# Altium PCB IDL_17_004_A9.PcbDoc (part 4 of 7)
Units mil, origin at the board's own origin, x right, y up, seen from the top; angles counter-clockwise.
Board outline 9493.25 x 7199.68 mil, 6 copper layers (Top Layer - SIG1, Layer 2 - GND1, Layer 3 - PWR1, Layer 4 - PWR2, Layer 5 - GND2, Bottom Layer - SIG2), stack 60.592 mil thick; 403 components, 274 nets, 1834 pads, 1849 vias.
Unrouted connection lines stored in the file: 1.
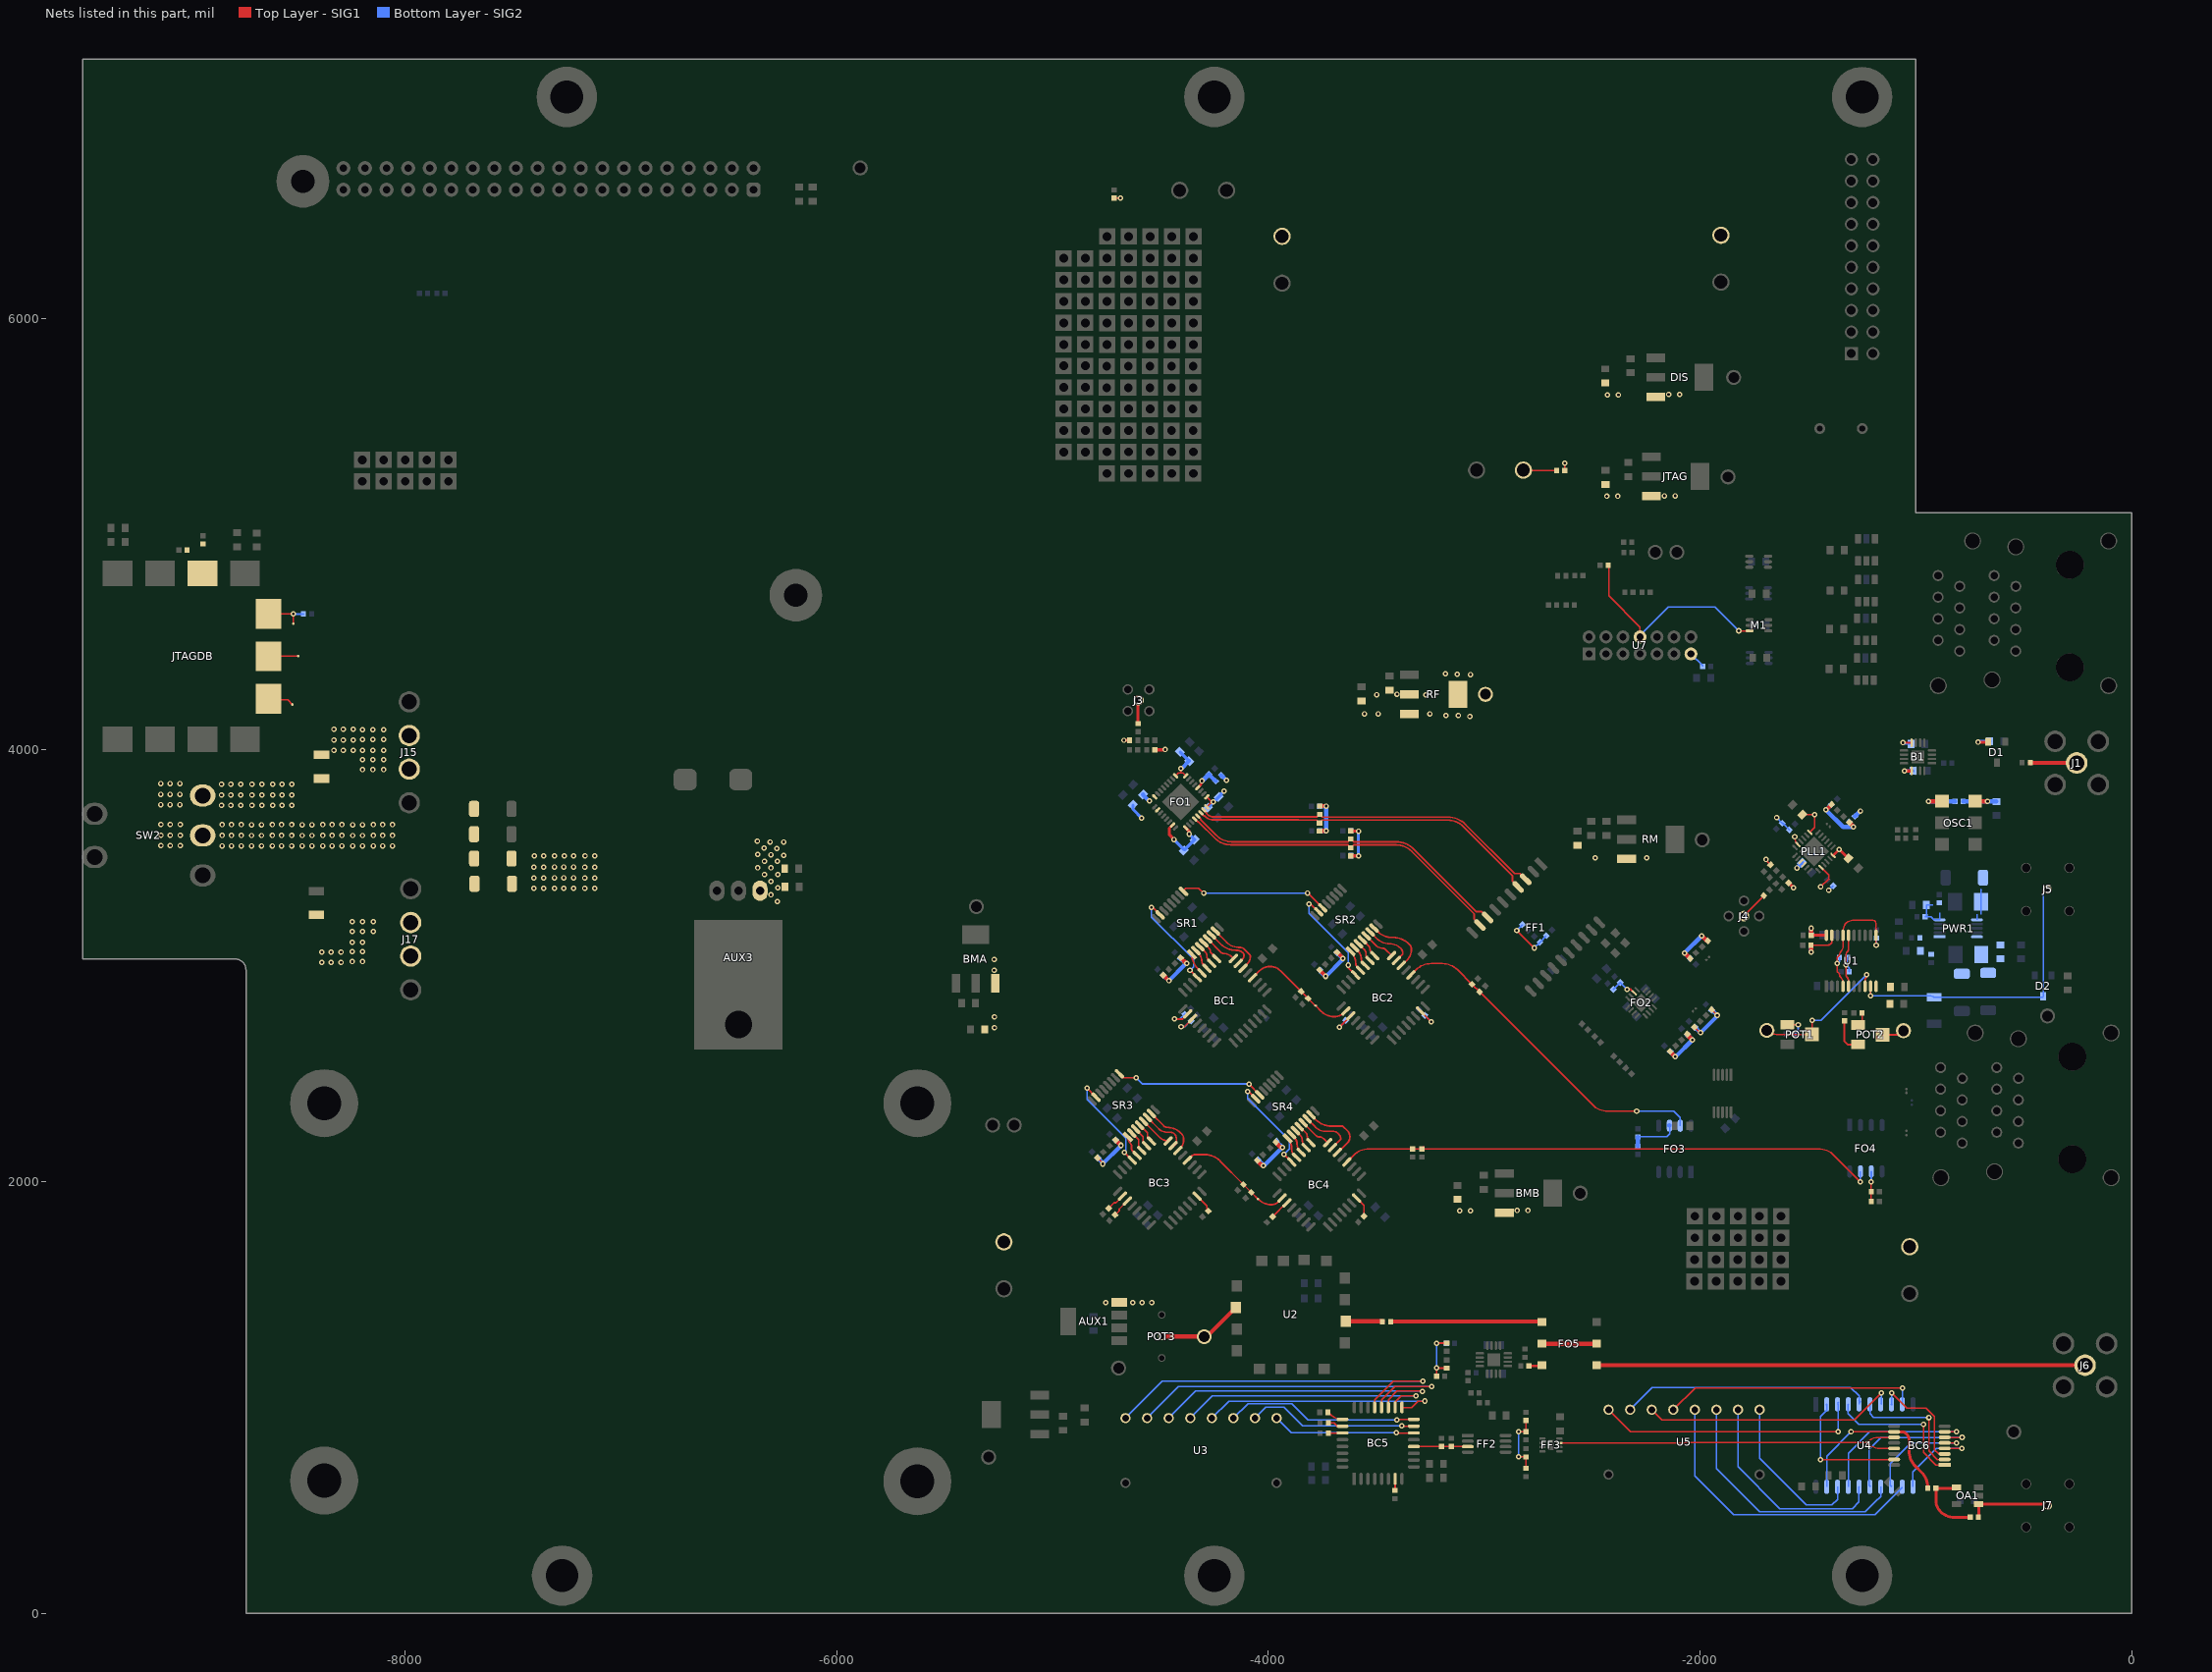
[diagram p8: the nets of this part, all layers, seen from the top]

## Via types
v1: diameter 25, hole 12, Top Layer - SIG1 to Bottom Layer - SIG2, tented both sides, 1502 vias
v2: diameter 25, hole 12, Top Layer - SIG1 to Bottom Layer - SIG2, 184 vias
v3: diameter 25.59, hole 11.81, Top Layer - SIG1 to Bottom Layer - SIG2, tented both sides, 163 vias

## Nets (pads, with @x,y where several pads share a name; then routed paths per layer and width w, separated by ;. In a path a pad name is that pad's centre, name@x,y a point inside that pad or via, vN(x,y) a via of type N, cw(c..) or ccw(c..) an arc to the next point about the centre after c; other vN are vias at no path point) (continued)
NetBC1_12: BC1.12 BC2.26 R65.1 R69.1 TP11.1 | length 575.6
  Top Layer - SIG1 w8: BC1.12@-4073.26,2944.9 -4041.26,2976.91 cw(c-3992.36,2928.02) -3992.36,2997.16 cw(c-3992.36,2928.12) -3943.54,2976.94 -3932.7,2966.09 R65.1@-3847.63,2881.02 -3816.38,2849.78 cw(c-3817.34,2848.82) R69.1@-3815.98,2848.82 -3783.52,2816.35 ccw(c-3781.35,2818.53) TP11.1@-3781.35,2815.45 -3755.1,2789.2 ccw(c-3695.35,2848.95) -3695.35,2764.45 ccw(c-3695.35,2832.52) -3647.22,2784.39 BC2.26@-3640.66,2790.95 ; BC1.12@-4055.93,2962.01 BC1.12@-4071.75,2946.19 ; BC1.12@-4071.75,2946.19 ccw(c-4001.14,2875.38) -4071.86,2946.09 -4073.15,2944.8 BC1.12@-4071.75,2946.19
NetBC1_14: BC1.14 SR1.7 | length 275.2
  Top Layer - SIG1 w8: SR1.7@-4245.62,3161.36 -4192.47,3108.21 ccw(c-4140.08,3160.6) -4140.08,3086.51 ccw(c-4137.68,3088.9) -4137.68,3085.52 -4133.6,3085.52 cw(c-4133.6,3051.63) -4109.64,3075.59 -4087.08,3053.03 cw(c-4094.32,3045.79) -4084.08,3045.79 -4084.08,3041.03 cw(c-4127.74,3041.03) -4096.87,3010.16 BC1.14@-4117.69,2989.34
NetBC1_15: BC1.15 SR1.6 | length 234.1
  Top Layer - SIG1 w8: SR1.6@-4263.71,3143.26 -4221.76,3101.31 ccw(c-4151.08,3171.99) -4151.08,3072.03 -4147.05,3072.03 cw(c-4147.05,3031.06) -4118.08,3060.03 cw(c-4130.15,3047.96) -4113.08,3047.96 -4113.08,3047.03 cw(c-4133.7,3047.03) -4119.12,3032.45 BC1.15@-4139.96,3011.61
NetBC1_16: BC1.16 SR1.5 | length 154.5
  Top Layer - SIG1 w8: SR1.5@-4281.81,3125.17 -4218.34,3061.7 ccw(c-4207.08,3072.96) -4207.08,3057.03 cw(c-4207.08,3004.66) -4170.05,3041.69 BC1.16@-4162.23,3033.88
NetBC1_17: BC1.17 SR1.4 | length 96.5
  Top Layer - SIG1 w8: SR1.4@-4299.9,3107.07 -4274.89,3082.06 cw(c-4288.91,3068.03) -4269.08,3068.03 ccw(c-4256.39,3068.03) -4265.36,3059.06 BC1.17@-4240.18,3033.88
NetBC1_18: BC1.18 SR1.3 | length 98.1
  Top Layer - SIG1 w8: SR1.3@-4318,3088.98 -4292.17,3063.15 cw(c-4309.28,3046.03) -4285.08,3046.03 ccw(c-4256.59,3046.03) -4276.74,3025.9 BC1.18@-4262.45,3011.61
NetBC1_19: BC1.19 SR1.2 | length 99.7
  Top Layer - SIG1 w8: SR1.2@-4336.09,3070.88 -4325.04,3059.82 cw(c-4366,3018.88) -4308.08,3018.88 ccw(c-4293.15,3018.88) BC1.19@-4303.71,3008.33 ; BC1.19@-4303.71,3008.32 BC1.19@-4284.72,2989.34
NetBC1_20: BC1.20 SR1.1 | length 101.3
  Top Layer - SIG1 w8: SR1.1@-4354.19,3052.79 ccw(c-4261.18,3052.79) -4326.95,2987.02 BC1.20@-4306.99,2967.07
NetBC1_21: BC1.21 SR1.15 | length 503.3
  Top Layer - SIG1 w6: v3(-4541.43,3271.28) -4541.43,3277.19 -4501.74,3237.49 SR1.15@-4501.74,3236.52 ; v3(-4363.27,2979.93) -4364.32,2980.98 -4365.45,2980.98 BC1.21@-4329.26,2944.8
  Bottom Layer - SIG2 w6: v3(-4541.43,3271.28) -4541.43,3274.83 -4541.63,3275.03 -4541.63,3225.81 -4346.75,3030.93 -4346.75,2996.45 v3(-4363.27,2979.93)
NetBC1_26: BC1.26 R68.1 | length 129
  Top Layer - SIG1 w8: v3(-4435.42,2753.84) -4397.73,2753.84 BC1.26@-4373.81,2777.76
  Bottom Layer - SIG2 w8: v3(-4435.42,2753.84) -4409.72,2753.84 R68.1@-4387.27,2776.29
NetBC1_27: BC1.27 R61.1 | length 125.9
  Top Layer - SIG1 w8: v3(-4404.35,2718.55) -4388.47,2718.55 BC1.27@-4351.54,2755.49
  Bottom Layer - SIG2 w8: v3(-4404.35,2718.55) -4387.7,2718.55 -4363.37,2742.88 cw(c-4357.32,2736.83) R61.1@-4357.32,2745.39
NetBC2_7: BC2.7 R64.1 | length 116.4
  Top Layer - SIG1 w8: BC2.7@-3295.46,2790.95 -3295.46,2790.08 v1(-3245.84,2740.47)
  Top Layer - SIG1 w20: v1(-3245.84,2740.47) v1@-3245.84,2743.12
  Bottom Layer - SIG2 w8: R64.1@-3275.09,2771.07 -3245.84,2741.82 v1(-3245.84,2740.47)
NetBC2_12: BC2.12 FO3.7 R66.1 R70.1 | length 1589.7
  Top Layer - SIG1 w6: BC2.12@-3340,2957.98 -3316.49,2981.49 cw(c-3245.78,2910.77) -3245.78,3010.77 -3194.48,3010.77 cw(c-3194.48,2910.77) -3123.77,2981.49 R70.1@-3057.01,2914.72 R66.1@-3021.65,2879.37 ; R66.1@-3021.65,2879.59 -2498.35,2356.29 ccw(c-2427.64,2427) -2427.64,2327 v3(-2294,2327)
  Bottom Layer - SIG2 w6: v3(-2294,2327) -2122.12,2327 -2092.5,2297.39 FO3.7@-2092.5,2259.71
NetBC2_14: BC2.14 SR2.7 | length 304
  Top Layer - SIG1 w8: SR2.7@-3510.77,3175.38 -3496.14,3160.74 ccw(c-3425.43,3231.45) -3425.43,3131.45 -3420.77,3131.45 cw(c-3420.77,3031.45) -3350.06,3102.16 -3345.12,3097.23 cw(c-3363.9,3078.45) -3337.35,3078.45 cw(c-3414.6,3078.45) -3359.97,3023.83 -3378.97,3004.83 cw(c-3384.54,3010.4) BC2.14@-3384.54,3002.52
NetBC2_15: BC2.15 SR2.6 | length 237.3
  Top Layer - SIG1 w8: SR2.6@-3528.87,3157.28 -3499.39,3127.8 ccw(c-3438.19,3189.01) -3438.19,3102.45 cw(c-3438.19,3030.41) -3387.25,3081.35 cw(c-3411.15,3057.45) -3377.35,3057.45 cw(c-3385.06,3057.45) -3379.6,3052.01 BC2.15@-3406.81,3024.79
NetBC2_16: BC2.16 SR2.5 | length 153.4
  Top Layer - SIG1 w8: SR2.5@-3546.97,3139.19 -3503.29,3095.51 ccw(c-3469.35,3129.46) -3469.35,3081.45 cw(c-3469.35,3067.26) -3459.31,3077.3 BC2.16@-3429.08,3047.07
NetBC2_17: BC2.17 SR2.4 | length 96.4
  Top Layer - SIG1 w8: SR2.4@-3565.06,3121.09 -3534.82,3090.85 cw(c-3548.02,3077.64) -3529.35,3077.64 ccw(c-3509.4,3077.64) -3523.5,3063.54 BC2.17@-3507.03,3047.07
NetBC2_18: BC2.18 SR2.3 | length 98
  Top Layer - SIG1 w8: SR2.3@-3583.16,3103 -3556.64,3076.49 cw(c-3576.68,3056.45) -3548.35,3056.45 ccw(c-3517.89,3056.45) BC2.18@-3539.44,3034.93 ; BC2.18@-3539.43,3034.92 BC2.18@-3529.3,3024.79
NetBC2_19: BC2.19 SR2.2 | length 99.6
  Top Layer - SIG1 w8: SR2.2@-3601.25,3084.9 -3583.46,3067.11 cw(c-3615.12,3035.45) -3570.35,3035.45 ccw(c-3536.17,3035.45) -3560.35,3011.3 BC2.19@-3551.57,3002.52
NetBC2_20: BC2.20 SR2.1 | length 101.1
  Top Layer - SIG1 w8: SR2.1@-3619.35,3066.81 -3618.93,3066.39 cw(c-3675.87,3009.45) -3595.35,3009.45 ccw(c-3576.76,3009.45) -3589.9,2996.31 BC2.20@-3573.84,2980.25
NetBC2_21: BC2.21 SR2.15 | length 479
  Top Layer - SIG1 w6: v3(-3812.35,3286.45) -3811.35,3285.45 -3801.8,3285.45 SR2.15@-3766.89,3250.54 ; v3(-3629.35,3003.45) -3629.35,2991.21 BC2.21@-3596.12,2957.98
  Bottom Layer - SIG2 w6: v3(-3812.35,3286.45) -3811.35,3286.45 -3811.35,3243.45 -3629.35,3061.45 v3(-3629.35,3003.45)
NetBC2_27: BC2.27 R62.1 | length 118.8
  Top Layer - SIG1 w8: v1(-3670.94,2716) -3618.39,2768.56 BC2.27@-3618.39,2768.68
  Top Layer - SIG1 w20: v1(-3670.94,2716) v1@-3670.94,2716.12
  Bottom Layer - SIG2 w8: v1(-3670.94,2716) -3642.23,2744.71 R62.1@-3642.23,2748.22
  Bottom Layer - SIG2 w20: v1(-3670.94,2716) v1@-3670.94,2716.12
NetBC3_7: BC3.7 R80.1 | length 82.1
  Top Layer - SIG1 w6: BC3.7@-4330.41,1933.06 -4284.61,1887.26 R80.1@-4284.61,1869.95
NetBC3_12: BC3.12 BC4.26 R82.1 R86.1 TP14.1 | length 542.6
  Top Layer - SIG1 w8: BC3.12@-4374.95,2100.09 -4356.99,2118.05 cw(c-4338.55,2099.61) -4338.55,2125.69 -4294.17,2125.69 cw(c-4294.17,2025.69) -4223.46,2096.4 ccw(c-4219.19,2096.4) -4222.21,2093.39 R86.1@-4115.82,1987 -4115.55,1987 R82.1@-4079.19,1950.63 -4048.23,1919.68 TP14.1@-4048.23,1919.59 ; TP14.1@-4044.22,1917.16 ccw(c-3987.55,1973.83) -3987.55,1893.69 ccw(c-3987.55,1941.79) -3953.54,1907.78 BC4.26@-3936.75,1924.57
NetBC3_14: BC3.14 SR3.7 | length 263.2
  Top Layer - SIG1 w8: SR3.7@-4542.21,2316.35 -4483.92,2258.05 ccw(c-4468.55,2273.42) -4468.55,2251.69 cw(c-4468.55,2162.36) -4405.39,2225.53 -4403.55,2223.69 cw(c-4430.11,2197.13) -4392.55,2197.13 -4392.55,2192.69 cw(c-4443.53,2192.69) -4407.48,2156.65 BC3.14@-4419.5,2144.63
NetBC3_15: BC3.15 SR3.6 | length 219.4
  Top Layer - SIG1 w8: SR3.6@-4560.68,2298.25 -4506.66,2244.23 ccw(c-4471.55,2279.34) -4471.55,2229.69 -4455.55,2229.69 cw(c-4455.55,2200.69) -4426.55,2200.69 -4426.55,2182.12 cw(c-4441.77,2182.12) BC3.15@-4441.77,2166.91
NetBC3_16: BC3.16 SR3.5 | length 150
  Top Layer - SIG1 w8: SR3.5@-4578.78,2280.16 -4504.6,2205.98 ccw(c-4464.04,2246.54) BC3.16@-4464.04,2189.18
NetBC3_17: BC3.17 SR3.4 | length 95.6
  Top Layer - SIG1 w6: SR3.4@-4596.87,2262.06 -4561.11,2226.3 -4561.11,2208.3 BC3.17@-4541.99,2189.18
NetBC3_18: BC3.18 SR3.3 | length 98.1
  Top Layer - SIG1 w6: SR3.3@-4614.97,2243.97 -4580.79,2209.79 -4580.79,2183.44 BC3.18@-4564.26,2166.91
NetBC3_19: BC3.19 SR3.2 | length 100.5
  Top Layer - SIG1 w6: SR3.2@-4633.06,2225.87 -4601.46,2194.27 -4601.46,2159.57 BC3.19@-4586.53,2144.63
NetBC3_20: BC3.20 SR3.1 | length 100
  Top Layer - SIG1 w8: SR3.1@-4651.16,2207.77 -4651.16,2207.12 ccw(c-4608.12,2207.12) -4638.55,2176.69 cw(c-4650.63,2164.62) -4633.55,2164.62 -4633.55,2150.5 ccw(c-4625.38,2150.5) -4631.16,2144.72 BC3.20@-4608.8,2122.36
NetBC3_21: BC3.21 SR3.15 | length 484.6
  Top Layer - SIG1 w6: v3@-4840.64,2433.44 SR3.15@-4798.71,2391.51 ; v1(-4667.19,2136.21) BC3.21@-4631.07,2100.09
  Bottom Layer - SIG2 w6: v3(-4840.64,2433.46) -4840.64,2381.29 -4661.04,2201.69 -4661.04,2142.37 v1(-4667.19,2136.21)
NetBC3_26: BC3.26 R85.1 | length 91.3
  Top Layer - SIG1 w8: R85.1@-4740.13,1877.01 -4714.28,1902.87 -4705.8,1902.87 BC3.26@-4675.61,1933.06 ccw(c-4675.61,1937.65) BC3.26@-4672.37,1934.4
NetBC3_27: BC3.27 R78.1 | length 87.9
  Top Layer - SIG1 w8: R78.1@-4709.69,1846.32 -4690.88,1865.13 -4690.88,1873.44 -4653.54,1910.79 BC3.27@-4653.34,1910.79
NetBC4_7: BC4.7 R81.1 | length 98.6
  Top Layer - SIG1 w8: BC4.7@-3591.55,1924.57 -3556.87,1889.89 R81.1@-3556.87,1840.35
NetBC4_12: BC4.12 FO4.7 R83.2 R87.1 | length 2516.9
  Top Layer - SIG1 w6: BC4.12@-3636.09,2091.6 -3605.24,2122.46 cw(c-3534.53,2051.74) -3534.53,2151.74 R87.1@-3331.32,2151.74 ; R83.2@-3288.25,2151.83 -1451.25,2151.83 cw(c-1451.25,2051.83) -1380.54,2122.54 v3(-1258,2000)
  Top Layer - SIG1 w8: R87.1@-3331.32,2151.74 R83.2@-3288.33,2151.74 ; R83.2@-3289.25,2150.83 R83.2@-3288.33,2151.74 ; R83.2@-3280.68,2159.4 R83.2@-3288.25,2151.83 R83.2@-3288.33,2151.74
  Bottom Layer - SIG2 w6: v3(-1258,2000) FO4.7@-1258,2047.55
NetBC4_14: BC4.14 SR4.7 | length 321.2
  Top Layer - SIG1 w8: SR4.7@-3802.62,2309.64 -3779.97,2286.98 ccw(c-3709.26,2357.69) -3709.26,2257.69 -3659.55,2257.69 cw(c-3659.55,2248.03) -3652.73,2254.86 -3633.55,2235.69 cw(c-3660.11,2209.13) -3622.55,2209.13 -3622.55,2206.69 cw(c-3658.77,2206.69) -3633.16,2181.08 -3676.31,2137.94 cw(c-3680.63,2142.26) BC4.14@-3680.63,2136.14
NetBC4_15: BC4.15 SR4.6 | length 252.5
  Top Layer - SIG1 w8: SR4.6@-3820.72,2291.54 -3783.04,2253.86 cw(c-3784.21,2252.69) -3782.55,2252.69 ccw(c-3736.68,2298.56) -3736.68,2233.69 -3701.7,2233.69 cw(c-3701.7,2199.55) -3677.55,2223.69 -3673.75,2219.88 cw(c-3695.94,2197.69) -3664.55,2197.69 -3702.25,2159.99 ccw(c-3700.67,2158.42) BC4.15@-3702.9,2158.42
NetBC4_16: BC4.16 SR4.5 | length 149.9
  Top Layer - SIG1 w8: SR4.5@-3838.81,2273.45 -3779.78,2214.41 ccw(c-3763.55,2230.63) -3763.55,2207.69 cw(c-3763.55,2180.23) -3744.13,2199.65 BC4.16@-3725.18,2180.69
NetBC4_17: BC4.17 SR4.4 | length 95.5
  Top Layer - SIG1 w8: SR4.4@-3856.91,2255.35 cw(c-3856.91,2251.26) -3854.02,2254.16 -3824.55,2224.69 cw(c-3833.1,2216.15) -3821.02,2216.15 -3821.02,2215.69 ccw(c-3779.7,2215.69) -3808.92,2186.48 BC4.17@-3803.12,2180.69
NetBC4_18: BC4.18 SR4.3 | length 96.4
  Top Layer - SIG1 w8: SR4.3@-3875.01,2237.25 -3850.71,2212.96 cw(c-3867.97,2195.69) -3843.55,2195.69 ccw(c-3797.41,2195.69) -3830.04,2163.06 BC4.18@-3825.4,2158.42
NetBC4_19: BC4.19 SR4.2 | length 97.9
  Top Layer - SIG1 w8: SR4.2@-3893.1,2219.16 -3880.23,2206.29 cw(c-3910.83,2175.69) -3867.55,2175.69 ccw(c-3820.1,2175.69) -3853.65,2142.13 BC4.19@-3847.67,2136.14
NetBC4_20: BC4.20 SR4.1 | length 100.2
  Top Layer - SIG1 w8: SR4.1@-3911.19,2201.06 cw(c-3956.2,2156.06) -3892.55,2156.06 -3892.55,2149.69 ccw(c-3860.69,2149.69) -3883.22,2127.16 BC4.20@-3869.94,2113.87
NetBC4_21: BC4.21 SR4.15 | length 482.6
  Top Layer - SIG1 w6: v3(-4095.56,2418.69) -4092.63,2418.69 SR4.15@-4058.74,2384.8 ; v3(-3927.25,2127.35) -3927.25,2126.64 BC4.21@-3892.21,2091.6
  Bottom Layer - SIG2 w6: v3(-4095.56,2418.69) -4095.56,2385.23 -3902.64,2192.32 -3902.64,2151.96 v3(-3927.25,2127.35)
NetBC4_27: BC4.27 R79.1 | length 95.3
  Top Layer - SIG1 w6: BC4.27@-3914.48,1902.3 BC4.27@-3912.15,1902.3
  Top Layer - SIG1 w8: R79.1@-3980.03,1838.66 -3915.32,1903.36 BC4.27@-3913.88,1903.36
NetBC5_7: BC5.7 R97.2 | length 53.7
  Top Layer - SIG1 w8: R97.2@-3413.1,570.08 -3413.1,623.69 BC5.7@-3413,623.79
NetBC5_12: BC5.12 FF2.3 R98.1 R101.1 | length 250.3
  Top Layer - SIG1 w6: BC5.12@-3326.48,773.48 -3198.25,773.48 R98.1@-3197.58,774.16
  Top Layer - SIG1 w8: R98.1@-3197.58,774.16 R101.1@-3153.58,774.16 -3079.86,774.16 cw(c-3079.86,769.8) FF2.3@-3076.77,772.89
NetBC5_14: BC5.14 U3.8 | length 664.2
  Top Layer - SIG1 w6: v3(-3406.51,837.25) -3405.64,836.38 BC5.14@-3326.39,836.38
  Bottom Layer - SIG2 w6: U3.8@-3962.12,905 -3894.37,837.25 v3(-3406.51,837.25)
NetBC5_15: BC5.15 U3.7 | length 793.4
  Top Layer - SIG1 w6: v3(-3382.88,868.74) -3382.02,867.88 BC5.15@-3326.39,867.88
  Bottom Layer - SIG2 w6: U3.7@-4062.12,905 -4011.12,956 -3928.15,956 -3840.9,868.74 v3(-3382.88,868.74)
NetBC5_16: BC5.16 U3.6 | length 901.1
  Top Layer - SIG1 w6: v3(-3405.52,897.29) -3403.43,899.38 BC5.16@-3326.39,899.38
  Bottom Layer - SIG2 w6: U3.6@-4162.12,905 -4095.12,972 -3891.02,972 -3816.3,897.29 v3(-3405.52,897.29) v3@-3409.6,901.37
NetBC5_17: BC5.17 U3.5 | length 1138.5
  Top Layer - SIG1 w6: BC5.17@-3382.33,956.47 ccw(c-3379.54,956.47) BC5.17@-3381.51,954.49 -3336.7,954.49 -3307.19,984 v3(-3276.12,984)
  Bottom Layer - SIG2 w6: U3.5@-4262.12,905 -4183.12,984 v3(-3276.12,984)
NetBC5_18: BC5.18 U3.4 | length 1223.1
  Top Layer - SIG1 w6: BC5.18@-3413.33,954.82 BC5.18@-3413,955.14 ; BC5.18@-3413,954.49 BC5.18@-3413,955.14 ; BC5.18@-3412.33,955.82 BC5.18@-3413,955.14 ; v3(-3316.12,1008) -3383.4,1008 -3413,978.4 BC5.18@-3413,955.14
  Bottom Layer - SIG2 w6: U3.4@-4362.12,905 -4259.12,1008 v3(-3316.12,1008)
NetBC5_19: BC5.19 U3.3 | length 1438.7
  Top Layer - SIG1 w6: BC5.19@-3444.33,954.67 BC5.19@-3444.5,954.49 -3444.5,989.56 -3404.26,1029.8 -3286.92,1029.8 v3(-3286.12,1029)
  Bottom Layer - SIG2 w6: U3.3@-4462.12,905 -4337.33,1029.8 -3286.92,1029.8 v3(-3286.12,1029)
NetBC5_20: BC5.20 U3.2 | length 1670.9
  Top Layer - SIG1 w6: BC5.20@-3476,954.49 -3476,989.56 -3414.55,1051 v3(-3244.12,1051)
  Bottom Layer - SIG2 w6: U3.2@-4562.12,905 -4416.12,1051 v3(-3244.12,1051)
NetBC5_21: BC5.21 U3.1 | length 1743.1
  Top Layer - SIG1 w6: BC5.21@-3507.49,954.49 -3507.49,989.56 -3421.05,1076 v3(-3284.12,1076)
  Bottom Layer - SIG2 w6: U3.1@-4662.12,905 -4491.12,1076 v3(-3284.12,1076)
NetBC5_25: BC5.25 R99.2 | length 76.7
  Top Layer - SIG1 w6: R99.2@-3723.85,931.98 -3715.37,923.51 ccw(c-3657.1,981.8) BC5.25@-3657.1,899.38
NetBC5_26: BC5.26 R100.2 | length 71.5
  Top Layer - SIG1 w6: R100.2@-3722.74,881.98 -3695.23,881.98 -3681.13,867.88 BC5.26@-3657.1,867.88
NetBC5_27: BC5.27 R96.2 | length 68.1
  Top Layer - SIG1 w6: R96.2@-3724.74,838.04 ccw(c-3720.75,842.03) -3720.75,836.38 BC5.27@-3657.1,836.38
NetBC6_1: BC6.1 U4.4 | length 670.5
  Top Layer - SIG1 w6: v1(-965.84,875.92) -965.84,745.76 -908.01,687.93 BC6.1@-867.35,687.93
  Bottom Layer - SIG2 w6: U4.4@-1313.84,964.29 -1312.6,965.53 U4.4@-1314.79,967.71 ; U4.4@-1313.79,968.71 U4.4@-1314.79,967.71 ; v1(-965.84,875.92) -1265.01,875.92 -1314.79,925.7 U4.4@-1314.79,967.71
NetBC6_2: BC6.2 U4.6 | length 582.9
  Top Layer - SIG1 w6: v3(-940.84,907.16) -940.84,752.45 -901.91,713.52 BC6.2@-867.35,713.52
  Bottom Layer - SIG2 w6: U4.6@-1213.84,962.73 U4.6@-1213.79,962.78 ; v3(-940.84,907.16) -1195.84,907.16 -1213.79,925.12 U4.6@-1213.79,962.78 ; U4.6@-1213.79,962.78 U4.6@-1213.79,968.71 -1214.79,969.71 -1214.97,969.9 -1213.99,970.88 -1209.84,966.73 U4.6@-1213.79,962.78
NetBC6_3: BC6.3 U4.8 | length 518.3
  Top Layer - SIG1 w6: v1(-1113.59,1022.1) -1042.66,951.16 -954.01,951.16 -914.69,911.84 -914.69,758.24 -895.56,739.11 BC6.3@-867.35,739.11 ccw(c-865.3,739.11) BC6.3@-865.3,737.06
  Bottom Layer - SIG2 w6: U4.8@-1114.79,969.71 -1114.79,967.22 cw(c-1114.79,966.22) -1113.79,966.22 -1111.62,968.38 -1113.59,970.35 v1(-1113.59,1022.1)
NetBC6_4: BC6.4 U4.11 | length 423.3
  Top Layer - SIG1 w6: BC6.4@-867.35,764.7 -867.35,765.21 v1(-786.82,765.21)
  Bottom Layer - SIG2 w6: U4.11@-1015.17,586.82 -1015.17,654.83 -904.79,765.21 v1(-786.82,765.21) v1@-786.97,765.06
NetBC6_5: BC6.5 U4.13 | length 513.2
  Top Layer - SIG1 w6: BC6.5@-867.35,790.29 -867.35,789.82 v3(-812.41,789.82)
  Bottom Layer - SIG2 w6: U4.13@-1113.79,586.82 -1120.48,593.52 -1120.48,694.18 -1024.84,789.82 v3(-812.41,789.82)
NetBC6_6: BC6.6 U4.15 | length 711.4
  Top Layer - SIG1 w6: BC6.6@-867.35,815.88 v3(-786.35,815.88)
  Bottom Layer - SIG2 w6: U4.15@-1210.05,586.82 -1216.94,593.71 -1216.94,761.06 -1162.12,815.88 v3(-786.35,815.88)
NetBC6_7: BC6.7 U4.17 | length 753.6
  Top Layer - SIG1 w6: BC6.7@-867.35,841.47 -867.35,841.98 v3(-812.41,841.98)
  Bottom Layer - SIG2 w6: U4.17@-1313.79,586.82 -1313.79,742.38 -1214.18,841.98 v3(-812.41,841.98)
NetBC6_10: BC6.10 R106.1 U4.19 | length 839.1
  Top Layer - SIG1 w6: v1(-1300.53,841.47) BC6.10@-1101.6,841.47
  Top Layer - SIG1 w13.5: BC6.10@-1101.6,841.47 -1067.32,841.47 cw(c-1067.32,809.34) -1044.6,832.06 cw(c-1073.57,803.09) -1032.6,803.09 -1032.6,753.48 ccw(c-932.6,753.48) -1003.31,682.77 -974.88,654.34 cw(c-1045.59,583.63) R106.1@-945.59,583.63
  Bottom Layer - SIG2 w6: U4.19@-1413.79,586.82 -1413.79,728.21 v1(-1300.53,841.47)
NetBC6_11: BC6.11 BC6.13 FF3.7 TP17.1 | length 1690.9
  Top Layer - SIG1 w6: FF3.7@-2651.84,790.51 -2071.49,790.51 ; -2070.84,791.16 TP17.1@-1228.6,791.16 ; -1186.69,815.42 ccw(c-1166.96,733.02) TP17.1@-1228.6,791.16 ; -1186.69,815.88 BC6.11@-1101.6,815.88 ; -1178.63,765.31 -1103.06,765.31 cw(c-1103.06,763.24) BC6.13@-1101.6,764.7 ; -1178.63,765.85 cw(c-1164.96,854.81) TP17.1@-1228.6,791.16
NetBC6_15: BC6.15 U4.2 | length 637.6
  Top Layer - SIG1 w6: v1(-1442.33,713.05) -1285.07,713.05 -1285.54,713.52 -1253.06,713.52 BC6.15@-1101.6,713.52
  Bottom Layer - SIG2 w6: v1(-1442.33,713.05) -1442.33,912.65 U4.2@-1413.79,941.19 ; U4.2@-1413.79,941.19 -1413.79,965.3 -1414.79,966.3 cw(c-1411.38,966.3) U4.2@-1413.79,968.71 U4.2@-1413.79,941.19
NetC18_1: C18.1 R3.1 R4.1 R5.1 | length 292
  Top Layer - SIG1 w20: v3(-1417.51,3722.57) -1416.51,3722.57 R3.1@-1391.51,3747.57 R3.1@-1391.51,3747.57 ; R4.1@-1308.79,3664.84 ccw(c-1303.91,3664.84) -1307.37,3661.4 v1(-1289.49,3643.53)
  Bottom Layer - SIG2 w8: C18.1@-1309.51,3665.84 ccw(c-1303.97,3665.84) -1307.89,3661.93 v1(-1289.49,3643.53)
  Bottom Layer - SIG2 w20: R5.1@-1392.24,3746.84 -1416.51,3722.57 v3(-1417.51,3722.57) -1338.47,3643.53 v1(-1289.49,3643.53)
NetC19_1: C19.1 J1.1 | length 215.2
  Top Layer - SIG1 w18: C19.1@-470.03,3940 J1.1@-256,3940
  Top Layer - SIG1 w20: C19.1@-470.84,3940.81 C19.1@-470.03,3940
NetC21_1: C21.1 FO1.4 R8.2 | length 129.6
  Top Layer - SIG1 w12: FO1.4@-4327.16,3824.94 -4317.54,3834.56 ccw(c-4339.27,3856.29) v1(-4308.54,3856.29)
  Bottom Layer - SIG2 w20: v1@-4307.83,3855.58 R8.2@-4275.94,3887.48 ; C21.1@-4244.9,3856.29 R8.2@-4274.4,3885.79 ; R8.2@-4274.4,3885.79 cw(c-4272.12,3888.07) -4275.34,3888.07 ccw(c-4272.12,3888.07) R8.2@-4274.4,3885.79
NetC22_2: C22.2 J3.1 | length 108.8
  Top Layer - SIG1 w14: C22.2@-4604.38,4122.67 -4604.38,4227.66 J3.1@-4601.71,4230.33
NetC23_2: C23.2 J4.1 | length 132.4
  Top Layer - SIG1 w8: J4.1@-1797.11,3230.64 cw(c-1791.39,3230.64) -1795.43,3234.69 -1724.51,3305.61 C23.2@-1705.06,3325.25
NetC24_1: C24.1 R18.1 R19.2 R20.2 | length 238.4
  Top Layer - SIG1 w20: R19.2@-3763.15,3624.22 -3762.28,3625.09 v1(-3732.51,3625.09) ; R20.2@-3762.77,3740.05 -3762.72,3740.09 v1(-3732.51,3740.09)
  Bottom Layer - SIG2 w20: C24.1@-3762.77,3740.05 -3731.56,3740.05 ccw(c-3729.26,3737.75) -3732.51,3737.75 v1(-3732.51,3625.09) ; R18.1@-3762.23,3625.09 v1(-3732.51,3625.09) ; v1@-3731.51,3625.09 v1(-3732.51,3625.09)
NetC25_1: C25.1 R34.1 R35.1 R36.1 | length 254.5
  Top Layer - SIG1 w15: R34.1@-3618.38,3625.55 -3616.92,3624.09 v1(-3582.13,3624.09) ; R35.1@-3617.33,3510.09 v1(-3583.13,3510.09)
  Bottom Layer - SIG2 w15: R36.1@-3617.52,3510.64 v1@-3583.58,3510.64 ; C25.1@-3617.52,3624.64 -3582.68,3624.64 ccw(c-3581.6,3623.56) -3583.13,3623.56 v1(-3583.13,3510.09)
NetC28_2: C28.2 C29.2 POT2.2 TP6.1 U1.10 | length 108.9
  Top Layer - SIG1 w8: POT2.2@-1154.45,2680.77 -1077.31,2680.77 TP6.1@-1058.25,2699.83
  Top Layer - SIG1 w20: POT2.2@-1154.45,2680.77 POT2.2@-1151.08,2677.4
NetC39_1: C39.1 R40.1 R41.2 R42.2 | length 261.1
  Top Layer - SIG1 w6: R41.2@-2027.03,2716.23 -2000.88,2690.08 v1(-1998.5,2690.08) ; R42.2@-1946.13,2796.97 -1946.13,2796.41 v3(-1921.01,2771.29)
  Bottom Layer - SIG2 w6: C39.1@-1946.54,2794.84 C39.1@-1944.56,2794.84 ; v3@-1923.64,2764.94 ccw(c-1929.99,2771.29) v3(-1921.01,2771.29)
  Bottom Layer - SIG2 w20: R40.1@-2025,2716.58 v1(-1998.5,2690.08) v3@-1923.64,2764.94 ; C39.1@-1944.56,2794.84 v3(-1921.01,2771.29)
NetC40_1: C40.1 FO2.2 R43.2 | length 128.9
  Top Layer - SIG1 w8: v1(-2338.62,2891.67) -2321.87,2891.67 FO2.2@-2305.57,2875.37
  Bottom Layer - SIG2 w8: R43.2@-2401.62,2891.04 C40.1@-2369.8,2922.86 v1(-2338.62,2891.67)
NetC41_1: C41.1 R44.1 R45.1 R46.1 | length 249
  Top Layer - SIG1 w20: R45.1@-2139.58,2603.51 ccw(c-2137.18,2603.51) -2138.89,2601.82 v1(-2115.78,2578.71) ; R44.1@-2059.44,2684.14 ccw(c-2050.34,2684.14) -2056.77,2677.71 v1(-2035.78,2656.71)
  Bottom Layer - SIG2 w20: R46.1@-2060.1,2682.35 v1@-2037.78,2660.02 ; v1(-2035.78,2656.71) -2112.36,2580.13 cw(c-2115.78,2583.54) v1(-2115.78,2578.71) -2138.14,2601.08 cw(c-2136.2,2603.02) C41.1@-2138.95,2602.88 ; C41.1@-2138.95,2602.88 cw(c-2136.2,2603.02) C41.1@-2138.95,2603.02 C41.1@-2138.95,2602.88
NetC44_1: C44.1 R55.2 R57.2 R58.2 | length 266.2
  Top Layer - SIG1 w20: R58.2@-4487.74,2956.6 -4486.64,2956.6 v1(-4461.08,2931.03) ; R57.2@-4406.35,3037.76 -4380.02,3011.42 ccw(c-4379.08,3012.36) -4379.08,3011.03 v3(-4378.08,3011.03)
  Bottom Layer - SIG2 w20: R55.2@-4486.99,2956.67 v1@-4461.35,2931.03 ; v1(-4461.08,2931.03) -4385.68,3006.43 v3@-4385.68,3014.18 ; C44.1@-4407.33,3035.83 v3@-4385.68,3014.18 ; v3(-4378.08,3011.03) cw(c-4378.08,3021.78) v3@-4385.68,3014.18
NetC45_1: C45.1 R56.2 R59.2 R60.2 | length 277
  Top Layer - SIG1 w20: R60.2@-3763.07,2980.73 -3733.8,2951.45 v3(-3733.93,2951.45) ; R59.2@-3681.71,3062.38 -3656.8,3037.47 ccw(c-3654.35,3039.92) -3654.35,3036.45 cw(c-3656.46,3036.45) v3(-3654.97,3034.96)
  Bottom Layer - SIG2 w20: R56.2@-3760.86,2980.8 ccw(c-3746.76,2980.8) -3756.73,2970.84 -3736.35,2950.45 cw(c-3733.93,2948.04) v3(-3733.93,2951.45) -3658.55,3026.83 ccw(c-3666.3,3034.58) v3@-3655.35,3034.58 ; C45.1@-3681.86,3061.09 v3@-3655.35,3034.58 ; v3(-3654.97,3034.96) v3@-3655.35,3034.58
NetC57_1: C57.1 R72.2 R74.2 R75.2 | length 268.5
  Top Layer - SIG1 w8: R75.2@-4791.44,2110.34 -4767.79,2086.69 v3(-4767.79,2082.46)
  Top Layer - SIG1 w20: R74.2@-4708.15,2193.64 -4707.77,2193.64 v3(-4682.83,2168.7)
  Bottom Layer - SIG2 w20: C57.1@-4790.47,2111.34 -4767.79,2088.65 v3(-4767.79,2082.46) -4683.21,2167.03 v3@-4683.21,2168.7 ; R72.2@-4708.15,2193.64 v3@-4683.21,2168.7 ; v3(-4682.83,2168.7) v3@-4683.21,2168.7
NetC58_1: C58.1 R73.2 R76.2 R77.2 | length 271.3
  Top Layer - SIG1 w20: R77.2@-4048.12,2094.2 -4028.6,2074.69 v3(-4023.55,2074.69) ; R76.2@-3962.32,2179.15 -3942.35,2159.18 v3(-3934.55,2159.18)
  Bottom Layer - SIG2 w20: C58.1@-4049.19,2102.33 -4023.55,2076.69 v3(-4023.55,2074.69) -4020.64,2074.69 -3936.14,2159.18 v3(-3934.55,2159.18) R73.2@-3963.06,2187.69
NetC68_1: C68.1 U2.10 | length 174.9
  Top Layer - SIG1 w20: U2.10@-3642.74,1353 C68.1@-3470.5,1353 ; U2.10@-3642.15,1353 cw(c-3639.74,1350.59) U2.10@-3639.74,1354
NetC68_2: C68.2 FO5.1 | length 702.2
  Top Layer - SIG1 w18: C68.2@-3433.28,1351.78 FO5.1@-2731.09,1351.78
NetC82_1: C82.1 R91.1 R94.2 R95.2 | length 293.8
  Top Layer - SIG1 w8: v3(-3221.12,1137) v3@-3220.76,1136.64 ; v3(-3221.12,1252) -3220.54,1252.58 R95.2@-3174.12,1252.58 ; C82.1@-3220.76,1099.98 v3@-3220.76,1136.64 ; R94.2@-3174.92,1137 R94.2@-3174.12,1136.2 -3220.33,1136.2 v3@-3220.76,1136.64
  Bottom Layer - SIG2 w8: v3(-3221.12,1137) v3(-3221.12,1252) -3175.72,1252 R91.1@-3175,1251.28
NetC83_1: C83.1 FO5.3 | length 61.4
  Top Layer - SIG1 w13: C83.1@-2793.22,1147 -2736.09,1147 FO5.3@-2733.09,1150
NetC85_1: C85.1 R102.1 R103.2 R104.2 | length 292.8
  Top Layer - SIG1 w6: v3(-2841.6,725.41) R103.2@-2806.21,725.4 C85.1@-2806.21,672.09 ; v3(-2841.6,841.41) -2841.96,841.77 R104.2@-2806.58,841.77 R102.1@-2806.58,893.97
  Bottom Layer - SIG2 w6: v3(-2841.6,725.41) v3(-2841.6,841.41)
NetC120_1: C120.1 L1.2 PWR1.10
NetC120_2: C120.2 D3.1 D4.2
NetC122_1: C122.1 PWR1.1 R121.1 R122.1
NetC125_1: C125.1 PWR1.5 R123.2 R124.2 | length 194.4
  Bottom Layer - SIG2 w6: -921,3282 -921.35,3282.35 C125.1@-952.34,3282.35 -952.34,3232.94 R124.2@-958.05,3227.23 -930.77,3227.23 -916.91,3213.37 PWR1.5@-891.04,3213.37 -891.04,3245.96 -891,3246
NetD2_3: D2.3 J5.1 R22.2 U1.9 | length 1341.2
  Top Layer - SIG1 w6: v3(-1210.57,2861.45) U1.9@-1210.57,2905.63
  Bottom Layer - SIG2 w6: v3(-1210.57,2861.45) -934.41,2861.45 cw(c-934.41,2836.69) R22.2@-916.91,2854.2 D2.3@-411,2854.2 ; D2.3@-411,2859 -411,3349.17 cw(c-404.17,3349.17) J5.1@-409,3354
NetD5_1: D5.1 D6.2 D7.1 D8.2@-7677.21,3380.05 SW2.2
  other v1: -8847.04,3556.07 -8804.04,3556.07 -8758.04,3556.07 -8709.72,3555.95 -8663.72,3555.95 -8613.72,3556.07 -8570.72,3556.07 -8524.72,3556.07 -8476.4,3555.95 -8430.4,3555.95 -8380.4,3556.07 -8337.4,3556.07 -8291.4,3556.07 -8242.01,3555.95 -8196.01,3555.95 -8146.01,3556.07 -8103.01,3556.07 -8057.01,3556.07 -9129.83,3556.75 -9086.83,3556.75 -9040.83,3556.75 -8847.04,3603.95 -8804.04,3603.95 -8758.04,3603.95 -8709.72,3603.84 -8663.72,3603.84 -8613.72,3603.95 -8570.72,3603.95 -8524.72,3603.95 -8476.4,3603.84 -8430.4,3603.84 -8380.4,3603.95 -8337.4,3603.95 -8291.4,3603.95 -8242.01,3603.84 -8196.01,3603.84 -8146.01,3603.95 -8103.01,3603.95 -8057.01,3603.95 -9129.83,3604.63 -9086.83,3604.63 -9040.83,3604.63 -8847.04,3653.95 -8804.04,3653.95 -8758.04,3653.95 -8709.72,3653.84 -8663.72,3653.84 -8613.72,3653.95 -8570.72,3653.95 -8524.72,3653.95 -8476.4,3653.84 -8430.4,3653.84 -8380.4,3653.95 -8337.4,3653.95 -8291.4,3653.95 -8242.01,3653.84 -8196.01,3653.84 -8146.01,3653.95 -8103.01,3653.95 -8057.01,3653.95 -9129.83,3654.63 -9086.83,3654.63 -9040.83,3654.63
NetD8_2: D8.2@-689.54,3408.33 L2.2 PWR1.6 | length 142.2
  Bottom Layer - SIG2 w6: PWR1.6@-717.81,3213.37 -717.81,3237.19 -717,3238 ; -700,3239 -699.43,3239.57 L2.2@-699.43,3297 -699.43,3353.17 -697.42,3355.18
NetF0_1: F0.1 J17.2 J17.3
  other v1: -8384.21,3016.11 -8341.21,3016.11 -8295.21,3016.11 -8243.97,3019.57 -8196.09,3019.57 -8384.21,3064 -8341.21,3064 -8295.21,3064 -8243.97,3065.57 -8196.09,3065.57 -8243.97,3108.57 -8196.09,3108.57 -8244.09,3158.57 -8196.2,3158.57 -8146.2,3158.57 -8244.09,3204.57 -8196.2,3204.57 -8146.2,3204.57
NetF1_1: F1.1 J15.2 J15.3
  other v1: -8196.81,3908.71 -8148.93,3908.71 -8098.93,3908.71 -8196.81,3954.71 -8148.93,3954.71 -8098.93,3954.71 -8329.07,3998.11 -8286.07,3998.11 -8240.07,3998.11 -8196.81,3997.71 -8148.93,3997.71 -8098.93,3997.71 -8329.07,4045.99 -8286.07,4045.99 -8240.07,4045.99 -8196.93,4047.71 -8149.05,4047.71 -8099.05,4047.71 -8196.93,4093.71 -8149.05,4093.71 -8099.05,4093.71 -8329.07,4095.99 -8286.07,4095.99 -8240.07,4095.99
NetFO3_6: FO3.6 R67.1 R71.1 | length 243.2
  Bottom Layer - SIG2 w6: R67.1@-2288.99,2207.72 -2154.71,2207.71 -2140.57,2221.85 -2140.57,2259.34 FO3.6@-2143.6,2262.37
  Bottom Layer - SIG2 w8: R71.1@-2289.96,2163.93 R71.1@-2289,2164.9
  Bottom Layer - SIG2 w20: R71.1@-2289,2164.9 R67.1@-2288.99,2207.72 ; FO3.6@-2143.6,2262.37 ccw(c-2139.84,2262.37) FO3.6@-2142.5,2259.71
NetFO4_6: FO4.6 R84.1 R88.1 | length 139.7
  Top Layer - SIG1 w8: v3(-1208.24,1999.13) -1208.24,1909.43 R88.1@-1207.59,1909.43
  Bottom Layer - SIG2 w8: v3(-1208.24,1999.13) -1207.72,1999.13 FO4.6@-1207.72,2047.84 FO4.6@-1207.61,2047.73
NetFO5_2: FO5.2 FO5.5 | length 253.9
  Top Layer - SIG1 w20: FO5.2@-2733.09,1250 FO5.5@-2479.15,1250
NetFO5_4: FO5.4 J6.1 | length 2262.2
  Top Layer - SIG1 w18: FO5.4@-2479.15,1150 J6.1@-217,1150
NetGPIO0_1: GPIO0.1 JTAGDB.5 | length 113.9
  Top Layer - SIG1 w6: JTAGDB.5@-8627.12,4231.93 -8542.95,4231.93 GPIO0.1@-8521.94,4210.92
NetGPIO1_1: GPIO1.1 JTAGDB.6 | length 114.7
  Top Layer - SIG1 w6: JTAGDB.6@-8609.4,4435.53 -8533.08,4435.53 -8533.22,4435.67 GPIO1.1@-8495.02,4435.67
NetGPIO2_1: GPIO2.1 JTAGDB.7 RA3.1 | length 245.6
  Top Layer - SIG1 w6: JTAGDB.7@-8622.44,4678.64 -8622.44,4629.93 v3(-8517.26,4629.93) GPIO2.1@-8517.26,4585.93
  Bottom Layer - SIG2 w8: v3(-8517.26,4629.93) -8516.85,4629.53 RA3.1@-8469.71,4629.53
NetJ7_1: J7.1 OA1.1 R105.2 | length 383.4
  Top Layer - SIG1 w6: R105.2@-711.6,445.43 R105.2@-709.32,447.71 ; J7.1@-396.06,506.06 J7.1@-390,500
  Top Layer - SIG1 w13.5: R105.2@-709.32,447.71 OA1.1@-709.32,506.06 J7.1@-396.06,506.06
NetJ11_1: J11.1 R108.2 | length 155.6
  Top Layer - SIG1 w6: J11.1@-2820.22,5294.73 -2819,5293.52 R108.2@-2665.1,5293.52
NetJTAGDB_9: JTAGDB.9 RA1.1 RA2.1
NetM1_6: M1.6 R115.1 U7.8 | length 1005
  Top Layer - SIG1 w6: R115.1@-2423,4854 -2423,4714 -2278.74,4569.74 U7.8@-2278.74,4523.74 ; v3(-1821,4552) -1771.05,4552 M1.6@-1770.98,4551.94
  Bottom Layer - SIG2 w6: U7.8@-2278.74,4523.74 -2278.74,4531.26 -2148,4662 -1931,4662 v3(-1821,4552)
NetOA1_4: OA1.4 R105.1 R106.2 | length 359.9
  Top Layer - SIG1 w6: OA1.4@-822.53,580.31 ccw(c-822.53,595.66) OA1.4@-811.68,584.8 ; R105.1@-754.39,451.71 cw(c-754.39,446.14) R105.1@-750.46,450.08
  Top Layer - SIG1 w13.5: OA1.4@-822.53,580.31 R106.2@-907.8,580.31 -907.8,523.23 ccw(c-835.43,523.23) -886.6,472.06 ccw(c-822.31,536.35) -822.31,445.43 R105.1@-749.4,445.43
NetOSC1_1: OSC1.1 R1.1 | length 190.4
  Top Layer - SIG1 w20: v3(-942.5,3761.68) -880.37,3761.68 OSC1.1@-880.05,3762 ccw(c-884.32,3766.28) OSC1.1@-878.28,3766.28
  Bottom Layer - SIG2 w20: v3(-942.5,3761.68) R1.1@-819.46,3761.68
NetPOT1_1: POT1.1 R17.2 | length 102
  Top Layer - SIG1 w8: POT1.1@-1596.1,2727.75 v3@-1545.9,2727.75
  Bottom Layer - SIG2 w8: R17.2@-1563.94,2683.44 -1545.88,2701.5 v3(-1545.88,2727.76)
NetPOT1_2: POT1.2 TP3.1 U1.8 | length 716.9
  Top Layer - SIG1 w6: TP3.1@-1691,2701 ccw(c-1646.27,2745.73) -1646.27,2682.47 POT1.2@-1481.93,2682.47 ; -1481.93,2716.28 POT1.2@-1481.93,2682.47 ; v3(-1481.25,2747.27) -1481.25,2684.1 cw(c-1483.56,2684.1) POT1.2@-1481.93,2682.47 ; U1.8@-1236.16,2905.63 -1236.16,2940.84 -1228.25,2948.75 v3(-1228.25,2959.83)
  Bottom Layer - SIG2 w6: v3@-1475.73,2747.27 v3(-1481.25,2747.27) -1440.81,2747.27 v3(-1228.25,2959.83)
NetPOT2_1: POT2.1 R33.1 | length 64.5
  Top Layer - SIG1 w6: POT2.1@-1269.77,2724.9 ccw(c-1269.77,2726.05) POT2.1@-1268.62,2726.05 -1250,2744.67 R33.1@-1250,2781
NetPOT2_3: POT2.3 R39.2 | length 164.4
  Top Layer - SIG1 w8: R39.2@-1332,2745.1 -1332,2650.13 -1317.37,2635.5 POT2.3@-1268.62,2635.5
NetPOT3_2: POT3.2 TP30.1 U2.2 | length 402.4
  Top Layer - SIG1 w20: POT3.2@-4494.29,1283.9 -4299.24,1283.9 TP30.1@-4297.63,1282.3 ; TP30.1@-4297.33,1282 TP30.1@-4297.63,1282.3 ; TP30.1@-4296.93,1283 TP30.1@-4297.63,1282.3 ; U2.2@-4150.15,1418 -4285.86,1282.3 TP30.1@-4297.63,1282.3
NetR21_1: R21.1 R28.1 R29.1 | length 224.1
  Top Layer - SIG1 w20: v1(-2072.56,3059.89) R28.1@-2046.43,3033.75 ; v3(-1992,3139.08) -1971.89,3118.97 ccw(c-1964.34,3126.51) R29.1@-1964.34,3115.84
  Bottom Layer - SIG2 w20: R21.1@-2046.43,3033.75 v1(-2072.56,3059.89) -1993.37,3139.08 v3(-1992,3139.08)
NetR23_2: R23.2 R24.2 R27.2 | length 231.6
  Top Layer - SIG1 w6: v3(-2849.23,3164.03) v3(-2768.23,3083.03)
  Bottom Layer - SIG2 w6: v3(-2849.23,3164.03) -2824.28,3188.98 ccw(c-2826.15,3190.85) R24.2@-2823.5,3190.85 ; v3(-2768.23,3083.03) -2768.23,3083.38 R23.2@-2741.86,3109.74 -2713.1,3138.51 ccw(c-2714.34,3139.75) R27.2@-2712.59,3139.75
NetR25_2: R25.2 R26.1 U1.20 | length 133.8
  Top Layer - SIG1 w14: R25.2@-1485.8,3141.85 U1.20@-1415.3,3141.85
  Top Layer - SIG1 w20: v3(-1486,3174) -1485.94,3173.94 R25.2@-1485.94,3142
  Bottom Layer - SIG2 w20: v3(-1486,3174) -1486,3143.13 R26.1@-1485.68,3142.81
NetR30_2: R30.2 R31.1 U1.19 | length 197.9
  Top Layer - SIG1 w8: R30.2@-1486.26,3096 -1409.49,3096 ccw(c-1409.49,3116.49) -1395,3102 ccw(c-1407.78,3114.78) -1389.71,3114.78 U1.19@-1389.71,3141.85
  Top Layer - SIG1 w20: v3(-1486.53,3063.58) R30.2@-1486.53,3095.73
  Bottom Layer - SIG2 w20: v3(-1486.53,3063.58) R31.1@-1486.53,3095.19
NetR32_1: R32.1 R37.2 U1.5 U1.16 | length 322
  Top Layer - SIG1 w6: v1(-1324,3004) -1324,3052.51 cw(c-1303.51,3052.51) -1318,3067 ccw(c-1330.22,3079.22) -1312.94,3079.22 U1.16@-1312.94,3141.85
  Top Layer - SIG1 w8: v1(-1324,3004) -1324,2959.49 ccw(c-1303.51,2959.49) -1318,2945 cw(c-1330.23,2932.77) -1312.94,2932.77 U1.5@-1312.94,2905.63 ; U1.16@-1312.94,3141.85 cw(c-1317.61,3137.18) U1.16@-1311,3137.18
  Bottom Layer - SIG2 w6: v1(-1324,3004) ccw(c-1340.9,3020.9) -1317,3020.9 R37.2@-1317,3039
  Bottom Layer - SIG2 w8: v1(-1324,3004) -1309.23,2989.23 R32.1@-1309.23,2972.31
NetR37_1: R37.1 R38.2 U1.4 U1.11 U1.17 | length 630.4
  Top Layer - SIG1 w6: v3(-1364.74,3010.69) -1364.74,3038.95 -1355,3048.69 cw(c-1327.69,3048.69) -1347,3068 ccw(c-1368.73,3089.73) -1338,3089.73 U1.17@-1338,3140.58 ; U1.17@-1338.53,3141.85 -1338.53,3161.47 cw(c-1288,3161.47) -1288,3212 -1204,3212 cw(c-1204,3193) -1185,3193 U1.11@-1184.98,3141.85 -1184.98,3095.7 v3(-1184.62,3095.34)
  Top Layer - SIG1 w8: v3(-1364.74,3010.69) -1364.74,2972.64 -1355,2962.9 ccw(c-1331.1,2962.9) -1348,2946 cw(c-1370.87,2923.13) -1338.53,2923.13 U1.4@-1338.53,2905.63 ; U1.17@-1338.53,3141.85 cw(c-1339.8,3140.58) U1.17@-1338,3140.58
  Bottom Layer - SIG2 w6: v3(-1364.74,3010.69) -1354.8,3020.64 R37.1@-1354.8,3039 ; v3(-1184.62,3095.34) -1182.65,3097.31 R38.2@-1182.65,3128.41
NetR109_1: R109.1 U7.13 | length 82.8
  Bottom Layer - SIG2 w6: U7.13@-2042.7,4469.55 U7.13@-2041.49,4470.76 ; U7.13@-2041.52,4446 U7.13@-2042.52,4445 -1988.21,4390.69 R109.1@-1988.21,4387.84
NetSR1_9: SR1.9 SR2.14 | length 696.8
  Top Layer - SIG1 w6: SR1.9@-4393.16,3345.1 -4397.13,3345.1 -4381.71,3360.52 -4322.57,3360.52 v1(-4299.57,3337.52) ; v1(-3818.57,3337.52) -3817.68,3337.52 SR2.14@-3748.8,3268.64
  Bottom Layer - SIG2 w6: v1(-4299.57,3337.52) v1(-3818.57,3337.52)
NetSR3_9: SR3.9 SR4.14 | length 690.5
  Top Layer - SIG1 w6: SR3.9@-4690.73,2500.08 SR3.9@-4690.13,2500.08 -4671.83,2481.77 v3(-4613.25,2481.77)
  Top Layer - SIG1 w8: v3(-4090.25,2452.77) -4090.25,2452.5 SR4.14@-4040.65,2402.9
  Bottom Layer - SIG2 w8: v3(-4613.25,2481.77) -4612.71,2481.77 -4583.71,2452.77 v3(-4090.25,2452.77)
NetU4_3: U4.3 U5.1 | length 1247
  Top Layer - SIG1 w6: U5.1@-2424.6,944.06 -2322.13,841.59 v3(-1361.17,841.59)
  Bottom Layer - SIG2 w6: v3(-1361.17,841.59) -1361.17,966.1 U4.3@-1363.79,968.71 -1361.62,970.88 -1363.59,972.85 U4.3@-1358.6,977.84
NetU4_5: U4.5 U5.2 | length 1170.4
  Bottom Layer - SIG2 w6: U5.2@-2324.6,944.06 -2221.5,1047.16 -1302.84,1047.16 -1263.79,1008.12 U4.5@-1263.79,985.85 ; U4.5@-1264.6,986.66 U4.5@-1263.79,985.85 ; U4.5@-1263.79,968.71 U4.5@-1263.79,985.85 ; U4.5@-1256.6,978.66 U4.5@-1263.79,985.85
NetU4_7: U4.7 U5.3 | length 1189.6
  Top Layer - SIG1 w6: U5.3@-2224.6,944.06 -2177.7,897.16 -1285.84,897.16 v1(-1160.84,1022.16)
  Bottom Layer - SIG2 w6: U4.7@-1163.79,968.71 -1160.84,971.67 v1(-1160.84,1022.16)
NetU4_9: U4.9 U5.4 | length 1181.2
  Top Layer - SIG1 w6: U5.4@-2124.6,944.06 -2023.5,1045.16 v3(-1062.84,1045.16)
  Bottom Layer - SIG2 w6: U4.9@-1063.79,968.71 -1064.6,969.53 -1062.84,971.29 v3(-1062.84,1045.16)
NetU4_12: U4.12 U5.5 | length 1396.1
  Bottom Layer - SIG2 w6: U5.5@-2024.6,944.06 -2024.6,637.06 -1844.7,457.16 -1190.95,457.16 -1131.69,516.42 -1064.79,583.33 U4.12@-1064.79,585.82
NetU4_14: U4.14 U5.6 | length 1190.3
  Bottom Layer - SIG2 w6: U5.6@-1924.6,944.06 -1924.6,671.06 -1724.7,471.16 -1235.44,471.16 -1190.3,516.31 -1163.79,542.81 U4.14@-1163.79,586.82
NetU4_16: U4.16 U5.7 | length 987
  Bottom Layer - SIG2 w6: U5.7@-1824.6,944.06 -1824.6,680.06 -1630.7,486.16 -1295.84,486.16 -1265.69,516.31 -1265.69,584.92 U4.16@-1263.79,586.82
NetU4_18: U4.18 U5.8 | length 743.9
  Bottom Layer - SIG2 w6: U5.8@-1724.6,944.06 -1724.6,718.93 -1508.73,503.06 -1389.79,503.06 -1363.79,529.06 U4.18@-1363.79,586.82
NIM_PWR: F1.2 SW2.3
  other v1: -8849.83,3743.89 -8806.83,3743.89 -8760.83,3743.89 -8708.96,3743.95 -8662.96,3743.95 -8612.96,3744.07 -8569.96,3744.07 -8523.96,3744.07 -9131.43,3746.93 -9088.43,3746.93 -9042.43,3746.93 -8849.83,3791.77 -8806.83,3791.77 -8760.83,3791.77 -8708.96,3791.83 -8662.96,3791.83 -8612.96,3791.95 -8569.96,3791.95 -8523.96,3791.95 -9131.43,3794.81 -9088.43,3794.81 -9042.43,3794.81 -8849.83,3841.77 -8806.83,3841.77 -8760.83,3841.77 -8708.96,3841.83 -8662.96,3841.83 -8612.96,3841.95 -8569.96,3841.95 -8523.96,3841.95 -9131.43,3844.81 -9088.43,3844.81 -9042.43,3844.81
"RAW PWR": AUX1.4 AUX3.1 BMA.3 BMB.3 C102.2 C103.2 C104.2 C105.2 C106.2 C112.1 C113.2 C115.2 D6.1 D8.1@-7503.98,3380.05 DIS.3 FAN3.1 FAN4.1 J9.1 J18.1 JTAG.3 R107.2 R108.1 RF.3 RM.3 | length 66.4
  Top Layer - SIG1 w6: R108.1@-2627.31,5293.52 v1(-2627.31,5328.95)
  Top Layer - SIG1 w8: R107.2@-4715.48,6556.86 v1@-4684.48,6556.86
  other v1: -4753.6,1440.06 -4627.6,1440.06 -4584.6,1440.06 -4540.6,1440.06 -3114.31,1864.63 -3063.62,1864.63 -2848.07,1866.6 -2797.38,1866.6 -5268.77,2713.27 -5268.77,2763.96 -5270.74,2979.51 -5270.74,3030.2 -6274,3298 -6305,3329 -7167.28,3358.93 -7121.28,3358.93 -7402.91,3360.05 -7356.91,3360.05 -7306.91,3360.16 -7263.91,3360.16 -7217.91,3360.16 -6273,3361 -6304,3392 -7167.28,3406.81 -7121.28,3406.81 -7402.91,3407.93 -7356.91,3407.93 -7306.91,3408.05 -7263.91,3408.05 -7217.91,3408.05 -6335,3423 -6273,3423 -6366,3454 -6304,3454 -7167.28,3456.81 -7121.28,3456.81 -7402.91,3457.93 -7356.91,3457.93 -7306.91,3458.05 -7263.91,3458.05 -7217.91,3458.05 -6274,3484 -6335,3485 -2486.76,3501.07 -2247.58,3501.07 -7165.28,3508.81 -7121.28,3508.81 -7400.91,3509.93 -7356.91,3509.93 -7306.91,3510.05 -7261.91,3510.05 -7217.91,3510.05 -6246,3512 -6305,3515 -6366,3516 -6277,3543 -6336,3546 -6308,3574 -6246,3574 -6367,3577 -3554.71,4167.71 -3490.73,4167.71 -3251.56,4167.71 -2432.67,5175.4 -2381.98,5175.4 -2166.43,5177.37 -2115.74,5177.37 -2429.11,5644.23 -2378.42,5644.23 -2146.14,5646.2 -2095.45,5646.2 -4685.48,6556.76
RF_3V3: B1.8 B1.13 C1.1 C2.2 C3.1 C4.2 C5.1 C6.2 C8.1 C9.2 C11.1 C12.2 C13.1 C14.2 C15.1 C16.2 C17.1 C18.2 C21.2 C107.2 D1.2 FO1.1 FO1.8 FO1.9 FO1.16 FO1.18 FO1.23 FO1.25 FO1.32 OSC1.6 PLL1.7 PLL1.11 PLL1.15 PLL1.16 PLL1.20 PLL1.24 R1.2 R6.2 R7.1 R9.2 R10.2 R13.2 R14.2 R125.1 RF3V.1 RF.2 RF.4 | length 2048.4
  Top Layer - SIG1 w6: v1@-4404.79,3908.86 v1(-4404.79,3913.56) ; v3(-1561.81,3598.57) -1562.51,3599.26 ccw(c-1510.66,3599.26) PLL1.11@-1547.33,3562.6 ; C13.1@-1527.03,3700.03 -1527.03,3694.48 -1520.51,3701 v3(-1469,3701) -1469,3640.93 PLL1.7@-1491.65,3618.28 ; v1(-1441.42,3365.57) -1403.47,3403.52 -1403.47,3420.93 -1437.96,3455.42 PLL1.20@-1440.15,3455.42
  Top Layer - SIG1 w8: FO1.9@-4429.66,3880.62 -4416.97,3893.3 -4405.21,3893.3 ; v1(-4404.79,3913.56) -4405.21,3913.15 -4405.21,3893.3 ; FO1.8@-4382.84,3880.62 -4395.52,3893.3 -4405.21,3893.3 ; FO1.32@-4285.41,3736.37 -4267.05,3754.72 v1@-4267.05,3759.77 ; FO1.1@-4285.4,3783.18 -4267.05,3764.83 v1@-4267.05,3759.77 ; v1@-4255.48,3759.77 v1@-4267.05,3759.77 ; v1(-1694.52,3492.73) -1694.52,3488.57 R13.2@-1673.88,3467.93 ; v1@-1062.95,4033.53 B1.8@-1020.53,4033.53
  Top Layer - SIG1 w13: -4458.37,3607.02 -4458.37,3638.06 FO1.23@-4443.57,3652.85 ; PLL1.24@-1384.47,3511.1 -1357.51,3538.06 -1354.06,3538.06 C12.2@-1313.97,3497.97
  Top Layer - SIG1 w14: v1(-4551.87,3763.52) v1@-4546.76,3763.52 ; FO1.25@-4382.84,3638.93 -4367.33,3623.42 v3(-4367.33,3610.62)
  Top Layer - SIG1 w15: v1(-4670.12,4044.99) R10.2@-4642.89,4044.99 ; R9.2@-4526.2,4000.99 v1@-4478.5,4000.99 ; -4458.37,3607.02 v1(-4436.71,3585.37) ; R14.2@-1590.79,3384.84 v1(-1566.9,3360.95) v1@-1564.77,3358.83 ; v1(-1053.23,3903.47) B1.13@-1020.53,3903.53 ; v1(-713,4036) -667.6,4036 D1.2@-665.37,4038.23
  Top Layer - SIG1 w20: OSC1.6@-726.5,3762 v1(-668.5,3762) ; v1(-668.5,3762) ccw(c-668.5,3764.26) -666.91,3762.66 -667.57,3762 v1(-668.5,3762)
  Bottom Layer - SIG2 w6: C6.2@-4341.59,3584.89 C6.2@-4341.59,3585.92 ; v1(-1404.79,3349.57) R6.2@-1383.15,3371.2 ; v1(-668.5,3762) v1@-666.24,3762 ; C3.1@-627.86,3762 C3.1@-627.54,3761.68
  Bottom Layer - SIG2 w8: v1(-4404.79,3913.56) v1@-4402.81,3913.56 ; v1(-1645.76,3686.12) R7.1@-1620.4,3660.76 cw(c-1620.4,3654.6) -1616.05,3658.96 R125.1@-1587.12,3630.03 ; v1(-1061.25,4033.83) ccw(c-1046.17,4048.91) -1046.17,4027.58 C11.1@-1023.48,4027.58
  Bottom Layer - SIG2 w14: C1.1@-4627.33,3745.47 -4627.33,3724.8 v1(-4587.3,3684.78) ; v3(-4367.33,3610.62) C6.2@-4341.59,3584.89
  Bottom Layer - SIG2 w15: v1(-4479.05,4001.85) v1@-4476.57,3999.37 ; v1(-4436.71,3585.37) -4388.91,3537.57 C6.2@-4341.59,3584.89 ; C5.1@-4408.43,3990.14 C107.2@-4366.01,3947.71 ; C15.1@-4280.72,3733.24 C16.2@-4231.23,3782.74 v1(-4204.81,3809.16) ; v1@-1257.82,3717.53 v1(-1257.49,3717.53) ; v1(-1053.23,3903.47) -1013.69,3903.47 C9.2@-1013.64,3903.53 ; v1(-713,4036) cw(c-703.34,4026.34) -703.34,4040 C4.2@-658.48,4040
  Bottom Layer - SIG2 w18: v1@-4402.81,3913.56 C107.2@-4367.47,3948.9
  Bottom Layer - SIG2 w20: C2.2@-4581.31,3793.76 -4581.31,3792.95 v1(-4551.87,3763.52) ; C21.2@-4218.17,3883.02 -4195.51,3860.36 ccw(c-4194.59,3861.28) -4194.59,3859.97 v1(-4193.61,3859) ; v1(-1551.51,3453.57) -1529.84,3475.24 ccw(c-1532.99,3478.39) C14.2@-1528.53,3478.39 ; C18.2@-1282.79,3692.57 v1@-1257.82,3717.53 ; R1.2@-780.69,3762.66 -780.02,3762 v1(-668.5,3762) ; v1@-666.24,3762 C3.1@-627.86,3762
  other v1: -1356.51,3538.57 -4255.33,3759.8 -3067,4156 -3178.34,4160.19 -3119.65,4159.48 -3270.27,4254.94 -3497.95,4256.35 -3403.91,4258.48 -3125.31,4350.4 -3063.79,4349.69 -3179.76,4352.52
RFCLK0-1_N: FF1.4 FO1.30 R19.1 | length 1647.8
  Top Layer - SIG1 w8: FO1.30@-4313.24,3708.53 -4302.65,3697.94 ccw(c-4295.79,3704.8) -4295.79,3695.09 -4292.4,3691.71 ccw(c-4254.97,3729.13) -4254.97,3676.2 -3861.12,3676.2 -3860.84,3675.92 ; -3858.34,3675.92 -3777.02,3675.92 R19.1@-3763.14,3662.03 ; R19.1@-3764.59,3663.45 R19.1@-3763.15,3662.02 ; R19.1@-3759.15,3666.02 R19.1@-3763.13,3662.03 ; FF1.4@-2851.88,3374.41 FF1.4@-2843.38,3365.92 -2869.88,3392.41 -2869.88,3417.86 -3097.82,3645.8 ccw(c-3168.53,3575.09) -3168.53,3675.09 -3717.31,3675.09 -3717.35,3675.13 -3750.04,3675.13 R19.1@-3763.13,3662.03
RFCLK0-1_P: FF1.3 FO1.31 R20.1 | length 1642.6
  Top Layer - SIG1 w8: FO1.31@-4299.32,3722.45 -4288.73,3711.86 cw(c-4295.59,3704.99) -4285.89,3704.99 -4282.5,3701.61 ccw(c-4254.97,3729.13) -4254.97,3690.2 -3858.62,3690.2 -3858.34,3689.92 -3775.1,3689.92 R20.1@-3763.93,3701.09 ; R20.1@-3762.77,3702.25 R20.1@-3763.93,3701.09 ; FF1.3@-2816.52,3409.76 FF1.3@-2808.03,3401.27 -2834.52,3427.76 -2859.98,3427.76 -3087.92,3655.7 ccw(c-3168.53,3575.09) -3168.53,3689.09 -3711.51,3689.09 -3711.55,3689.13 -3751.98,3689.13 R20.1@-3763.93,3701.09
RFCLK1-1_N: FF1.9 FO1.28 R35.2 | length 1553.5
  Top Layer - SIG1 w8: FO1.28@-4341.08,3680.69 -4330.49,3670.1 ccw(c-4323.63,3676.96) -4323.63,3667.25 -4246.44,3590.06 ccw(c-4175.73,3660.77) -4175.73,3560.77 -3631.81,3560.77 R35.2@-3618.13,3547.09 -3604.8,3560.42 -3407.26,3560.42 cw(c-3407.26,3460.78) -3336.81,3531.24 -3046.65,3241.09 -3046.65,3215.63 FF1.9@-3020.16,3189.14 FF1.9@-3028.65,3197.63
RFCLK1-1_P: FF1.8 FO1.29 R34.2 | length 1553.6
  Top Layer - SIG1 w8: FO1.29@-4327.16,3694.61 -4316.57,3684.02 cw(c-4323.43,3677.15) -4313.73,3677.15 -4241.03,3604.45 ccw(c-4170.31,3675.16) -4170.31,3575.16 ; FF1.8@-2993.3,3232.99 FF1.8@-2984.81,3224.5 -3011.3,3250.99 -3036.75,3250.99 -3326.9,3541.14 ccw(c-3407.26,3460.78) -3407.26,3574.42 -3605.05,3574.42 R34.2@-3618.38,3587.75 -3631.36,3574.77 -4169.38,3574.77 ; -4170.31,3575.16 ccw(c-4169.38,3576.1) -4169.38,3574.77 ; -4170.31,3575.16 ccw(c-4169.38,3576.1) -4169.38,3574.77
